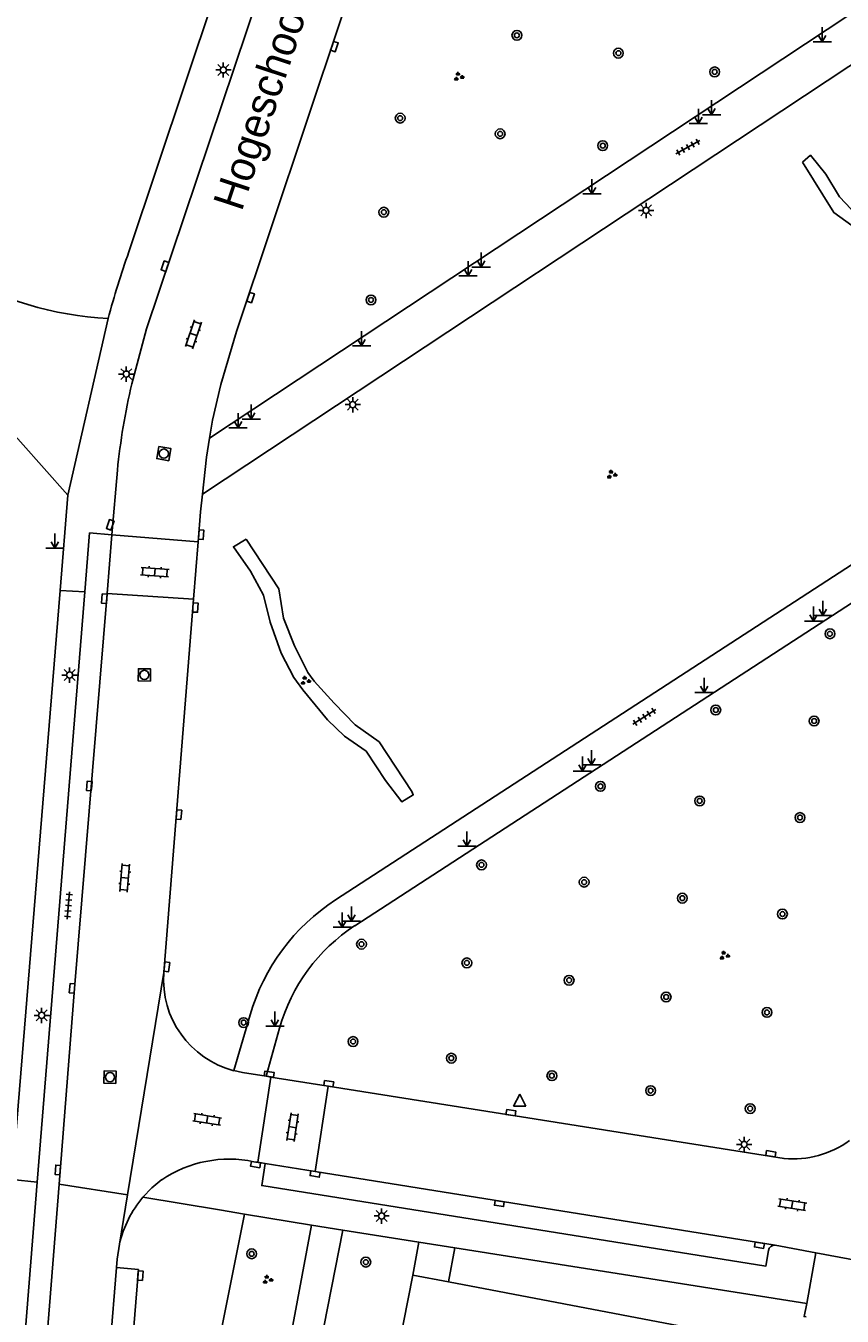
# Model space of a CAD drawing. Extents: x 131000 to 133014, y 396499 to 399001.
# Drawn here: x 131320.7 to 131387.5, y 397286.7 to 397392.1 of the extents above; entities that cross this region are included whole.
import ezdxf

# ---------------------------------------------------------------- set-up
doc = ezdxf.new("R2010")
doc.units = 0
for name, color, linetype in [('gg-afsc-hekwerk', 7, 'Continuous'), ('gg-anno-openbare ruimte label', 7, 'Continuous'), ('gg-bbg-hoofdgebouw', 7, 'Continuous'), ('gg-knt-verharding', 7, 'Continuous'), ('gg-knt-verharding nz', 7, 'Continuous'), ('gt-grn-groengrens', 7, 'Continuous'), ('gt-grn-weggrens', 7, 'Continuous'), ('gt-symb-boom', 7, 'Continuous'), ('gt-symb-groenvak', 7, 'Continuous'), ('gt-symb-klinker verharding', 7, 'Continuous'), ('gt-symb-kolk', 7, 'Continuous'), ('gt-symb-lichtmast', 7, 'Continuous'), ('gt-symb-markant object', 7, 'Continuous'), ('gt-symb-rioolschacht', 7, 'Continuous'), ('gt-symb-tegel verharding', 7, 'Continuous'), ('gt-symb-waterafsluiter', 7, 'Continuous')]:
    doc.layers.add(name, color=color, linetype=linetype)

# ---------------------------------------------------------------- blocks, each defined once
blk = doc.blocks.new('gt0-MARKOB')
at = {"layer": 'gt-symb-markant object'}
for p, q in [((0, 0), (0, 1.2)), ((-0.75, 0), (0.75, 0)), ((0, 0), (-0.3, 0.52)), ((0, 0), (0.3, 0.52))]:
    blk.add_line(p, q, dxfattribs=at)
blk = doc.blocks.new('gt0-BOOM')
at = {"layer": 'gt-symb-boom'}
for radius in [0.4, 0.2]:
    blk.add_circle((0, 0), radius, dxfattribs=at)
blk = doc.blocks.new('gt0-LMAST')
at = {"layer": 'gt-symb-lichtmast'}
for p, q in [((-0.18, 0.17), (-0.45, 0.44)), ((-0.01, 0.25), (-0.01, 0.62)), ((0.17, 0.17), (0.44, 0.44)), ((-0.26, 0), (-0.63, 0)), ((-0.18, -0.18), (-0.45, -0.45)), ((-0.01, -0.25), (-0.01, -0.63)), ((0.44, -0.45), (0.17, -0.18)), ((0.24, 0), (0.62, 0))]:
    blk.add_line(p, q, dxfattribs=at)
blk.add_circle((-0.01, 0), 0.25, dxfattribs=at)
blk = doc.blocks.new('gt0-TEG1')
at = {"layer": 'gt-symb-tegel verharding'}
for p, q in [((-1.12, 0), (1.12, 0)), ((-0.9, -0.25), (-0.9, 0.25)), ((-0.45, -0.25), (-0.45, 0.25)), ((0, -0.25), (0, 0.25)), ((0.45, -0.25), (0.45, 0.25)), ((0.9, -0.25), (0.9, 0.25))]:
    blk.add_line(p, q, dxfattribs=at)
blk = doc.blocks.new('gt0-GRVAK')
at = {"layer": 'gt-symb-groenvak'}
for p, q in [((-0.11, 0.19), (-0.23, 0.24)), ((-0.18, 0.15), (0.09, 0.15)), ((-0.09, 0.21), (-0.16, 0.32)), ((-0.05, 0.21), (-0.05, 0.39)), ((0, 0.21), (0.06, 0.32)), ((0.02, 0.19), (0.13, 0.24)), ((0.26, -0.05), (0.2, 0.06)), ((0.3, -0.05), (0.3, 0.13)), ((0.35, -0.05), (0.41, 0.06)), ((-0.24, -0.23), (-0.36, -0.18)), ((-0.32, -0.26), (-0.05, -0.26)), ((-0.23, -0.21), (-0.29, -0.09)), ((-0.18, -0.2), (-0.18, -0.02)), ((-0.14, -0.21), (-0.07, -0.09)), ((-0.12, -0.23), (0, -0.18)), ((0.24, -0.07), (0.12, -0.02)), ((0.17, -0.11), (0.44, -0.11)), ((0.37, -0.07), (0.49, -0.02))]:
    blk.add_line(p, q, dxfattribs=at)
blk = doc.blocks.new('gt0-KL1')
at = {"layer": 'gt-symb-klinker verharding'}
for p, q in [((-1.15, 0.3), (1.15, 0.3)), ((-1, -0.3), (-1, 0.3)), ((-0.5, 0.3), (-0.5, 0.45)), ((0, -0.3), (0, 0.3)), ((0.5, 0.3), (0.5, 0.45)), ((1, -0.3), (1, 0.3)), ((-1.15, -0.3), (1.15, -0.3)), ((-0.5, -0.45), (-0.5, -0.3)), ((0.5, -0.45), (0.5, -0.3))]:
    blk.add_line(p, q, dxfattribs=at)
blk = doc.blocks.new('gt0-KOLK')
at = {"layer": 'gt-symb-kolk'}
blk.add_lwpolyline([(0, 0), (0.38, 0), (0.38, 0.4), (-0.38, 0.4), (-0.38, 0), (0, 0)], dxfattribs=at)
blk = doc.blocks.new('gt0-RS')
at = {"layer": 'gt-symb-rioolschacht'}
blk.add_lwpolyline([(-0.5, -0.5), (0.5, -0.5), (0.5, 0.5), (-0.5, 0.5)], close=True, dxfattribs=at)
blk.add_circle((0, 0), 0.375, dxfattribs=at)
blk = doc.blocks.new('gt0-WAFSL')
at = {"layer": 'gt-symb-waterafsluiter'}
for p, q in [((-0.5, -0.33), (0, 0.67)), ((0, 0.67), (0.5, -0.33)), ((0.5, -0.33), (-0.5, -0.33))]:
    blk.add_line(p, q, dxfattribs=at)

msp = doc.modelspace()

# ---------------------------------------------------------------- linework, layer by layer
at = {"layer": 'gg-afsc-hekwerk'}
for points in [[(131384.22, 397381.01), (131386.78, 397376.88), (131388.74, 397375.46), (131390.5, 397373.78), (131392.15, 397372), (131392.69, 397371.15), (131394.44, 397366.61), (131394.7, 397364.19), (131397.27, 397360.07)], [(131352.28, 397329.56), (131349.62, 397333.62), (131347.65, 397335.02), (131345.93, 397336.77), (131344.31, 397338.57), (131343.79, 397339.29), (131342.69, 397341.47), (131341.81, 397343.74), (131341.41, 397346.13), (131338.74, 397350.18)]]:
    msp.add_lwpolyline(points, dxfattribs=at)
at = {"layer": 'gg-bbg-hoofdgebouw'}
msp.add_line((131352.36, 397290.02), (131355.29, 397289.47), dxfattribs=at)
for points in [[(131344.63, 397283.38), (131350.82, 397282.16), (131352.36, 397290.02)], [(131355.29, 397289.47), (131374.14, 397285.89), (131373.36, 397281.77), (131380.43, 397280.44), (131378.86, 397272.17)]]:
    msp.add_lwpolyline(points, dxfattribs=at)
at = {"layer": 'gg-knt-verharding'}
for p, q in [((131340.86, 397408.65), (131329.16, 397373.66)), ((131335.76, 397358.44), (131403.77, 397403.49)), ((131408.39, 397402.32), (131335.18, 397353.86)), ((131329.4, 397362.88), (131330.61, 397367.38)), ((131324.17, 397353.78), (131314.75, 397364.39)), ((131400.59, 397356.11), (131346.05, 397320.69)), ((131328.22, 397355.83), (131327.77, 397350.55)), ((131324.17, 397353.78), (131323.53, 397345.99)), ((131399.92, 397352.55), (131347.63, 397318.59)), ((131334.83, 397349.97), (131327.77, 397350.55)), ((131334.83, 397349.97), (131334.45, 397345.27)), ((131323.53, 397345.99), (131319.61, 397297.84)), ((131325.56, 397345.88), (131321.67, 397297.63)), ((131327.38, 397345.75), (131334.45, 397345.27)), ((131334.45, 397345.27), (131332.02, 397314.77)), ((131339.07, 397311.3), (131337.74, 397306.74)), ((131341.47, 397310.21), (131340.38, 397306.28)), ((131340.38, 397306.28), (131340.77, 397306.22)), ((131340.77, 397306.22), (131339.71, 397299.25)), ((131340.77, 397306.22), (131345.45, 397305.48)), ((131344.38, 397298.5), (131345.45, 397305.48)), ((131345.45, 397305.48), (131382.72, 397299.57)), ((131339.71, 397299.25), (131339.38, 397299.3)), ((131340.29, 397299.15), (131339.71, 397299.25)), ((131338.61, 397295.02), (131344.08, 397294.12)), ((131346.66, 397293.71), (131344.63, 397283.38)), ((131352.87, 397292.73), (131346.66, 397293.71)), ((131355.82, 397292.26), (131352.87, 397292.73)), ((131384.57, 397287.7), (131355.82, 397292.26)), ((131385.33, 397291.85), (131382, 397292.47)), ((131390.4, 397290.9), (131385.33, 397291.85))]:
    msp.add_line(p, q, dxfattribs=at)
for points in [[(131330.61, 397367.38), (131346.03, 397413.27), (131346.46, 397417.82)], [(131335.76, 397358.44), (131336, 397359.91), (131336.67, 397362.82), (131337.97, 397367.17), (131352.27, 397409.97)], [(131335.76, 397358.44), (131335.5, 397356.9), (131335.18, 397353.86)], [(131335.18, 397353.86), (131335.02, 397352.42), (131334.83, 397349.97)], [(131327.77, 397350.55), (131325.95, 397350.7), (131325.56, 397345.88)], [(131340.38, 397306.28), (131338.44, 397306.59), (131337.74, 397306.74)], [(131340.29, 397299.15), (131340.02, 397297.34), (131381.22, 397290.75), (131381.44, 397292.05)], [(131320.36, 397259.14), (131318.57, 397259.24), (131321.67, 397297.63)], [(131331.85, 397297.83), (131331.04, 397297.15), (131330.31, 397296.39)], [(131344.08, 397294.12), (131342.19, 397283.89), (131336.59, 397284.94), (131338.61, 397295.02)], [(131328.39, 397292.57), (131328.19, 397291.32), (131328.14, 397290.65)], [(131322.9, 397203.91), (131329.94, 397290.48), (131328.14, 397290.65)], [(131384.53, 397286.61), (131384.36, 397286.64), (131384.57, 397287.7)]]:
    msp.add_lwpolyline(points, dxfattribs=at)
for centre, radius, start, end in [((131328.85, 397395.81), 27.62, 212.161, 267.13), ((131396.95, 397349.62), 71.93, 160.4732, 165.0154), ((131381.85, 397350.44), 53.9, 166.6634, 174.267), ((131355.2, 397306.6), 16.8, 122.9954, 163.7311), ((131355.66, 397306.25), 14.72, 123.015, 164.395), ((131339.67, 397314.16), 7.67, 175.4568, 255.4497), ((131383.48, 397307.32), 7.79, 264.3662, 306.1476), ((131337.35, 397289.67), 9.84, 78.1055, 123.9871), ((131337.31, 397290.48), 9.16, 139.8111, 166.7828), ((131381.94, 397291.96), 0.506, 83.4052, 170.2357)]:
    msp.add_arc(centre, radius, start, end, dxfattribs=at)
at = {"layer": 'gg-knt-verharding nz'}
for p, q in [((131327.77, 397350.55), (131327.38, 397345.75)), ((131344.38, 397298.5), (131340.29, 397299.15)), ((131382, 397292.47), (131344.38, 397298.5)), ((131328.14, 397290.65), (131326.38, 397269.16))]:
    msp.add_line(p, q, dxfattribs=at)
for points in [[(131327.38, 397345.75), (131324.72, 397313.45), (131323.46, 397297.47)], [(131323.46, 397297.47), (131322.48, 397285.11), (131321.22, 397270.23), (131321.24, 397269.59)]]:
    msp.add_lwpolyline(points, dxfattribs=at)
at = {"layer": 'gt-grn-groengrens'}
for p, q in [((131352.36, 397290.02), (131352.87, 397292.73)), ((131355.29, 397289.47), (131355.82, 397292.26))]:
    msp.add_line(p, q, dxfattribs=at)
for points in [[(131397.27, 397360.07), (131397.44, 397359.87), (131398.26, 397360.39), (131396.74, 397362.93), (131395.84, 397365.09), (131395.54, 397367.07), (131393.81, 397371.52), (131392.89, 397372.97), (131391.31, 397374.73), (131389.51, 397376.3), (131388.22, 397377.15), (131387.24, 397378.17), (131386.13, 397380.01), (131384.88, 397381.57), (131384.22, 397381.01)], [(131338.74, 397350.18), (131337.71, 397349.57), (131339.11, 397347.56), (131340.16, 397345.6), (131340.7, 397343.41), (131341.61, 397340.87), (131342.64, 397338.89), (131343.37, 397337.88), (131345.39, 397335.42), (131346.78, 397334.07), (131348.56, 397332.85), (131350.14, 397330.47), (131351.47, 397328.72), (131352.41, 397329.28), (131352.28, 397329.56)]]:
    msp.add_lwpolyline(points, dxfattribs=at)
at = {"layer": 'gt-grn-weggrens'}
for p, q in [((131327.47, 397368.22), (131324.17, 397353.78)), ((131325.56, 397345.88), (131323.53, 397345.99)), ((131329.05, 397296.59), (131332.02, 397314.77)), ((131319.61, 397297.84), (131321.67, 397297.63)), ((131323.46, 397297.47), (131329.05, 397296.59)), ((131329.05, 397296.59), (131328.39, 397292.57)), ((131336.56, 397295.36), (131330.31, 397296.39)), ((131338.61, 397295.02), (131336.56, 397295.36)), ((131346.66, 397293.71), (131344.08, 397294.12)), ((131385.33, 397291.85), (131384.57, 397287.7))]:
    msp.add_line(p, q, dxfattribs=at)

# ---------------------------------------------------------------- block references
at = {"layer": 'gt-symb-boom'}
for p in [(131360.88, 397391.37), (131369.18, 397389.91), (131377.05, 397388.38), (131351.34, 397384.6), (131359.51, 397383.32), (131367.9, 397382.35), (131350, 397376.91), (131348.95, 397369.74), (131386.47, 397342.45), (131377.14, 397336.22), (131385.18, 397335.32), (131367.71, 397329.98), (131375.82, 397328.79), (131384.02, 397327.43), (131357.99, 397323.56), (131366.38, 397322.15), (131374.4, 397320.84), (131382.59, 397319.54), (131348.18, 397317.08), (131356.79, 397315.55), (131365.15, 397314.13), (131373.08, 397312.76), (131381.32, 397311.5), (131338.54, 397310.67), (131347.49, 397309.12), (131355.52, 397307.76), (131363.74, 397306.33), (131371.81, 397305.11), (131379.95, 397303.64), (131339.2, 397291.77), (131348.53, 397291.09)]:
    msp.add_blockref('gt0-BOOM', p, dxfattribs=at)
at = {"layer": 'gt-symb-groenvak'}
for p in [(131356.11, 397387.99), (131368.62, 397355.47), (131343.58, 397338.61), (131377.83, 397316.15), (131340.48, 397289.66)]:
    msp.add_blockref('gt0-GRVAK', p, dxfattribs=at)
at = {"layer": 'gt-symb-klinker verharding'}
for p, rotation in [((131334.44, 397366.92), 71.51067367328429), ((131331.28, 397347.49), -3.9550376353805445), ((131328.82, 397322.51), 85.29819168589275), ((131335.56, 397302.75), -9.094804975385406), ((131342.54, 397302.12), -98.62422873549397), ((131383.39, 397295.79), -9.094804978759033)]:
    msp.add_blockref('gt0-KL1', p, dxfattribs=dict(at, rotation=rotation))
at = {"layer": 'gt-symb-kolk'}
for p, rotation in [((131345.77, 397390.51), -108.59797779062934), ((131332.3, 397372.43), 69.87983420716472), ((131338.92, 397370), -109.21431186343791), ((131327.82, 397351.29), 70.96692019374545), ((131334.87, 397350.57), -94.70180831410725), ((131327.36, 397345.3), 85.75513794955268), ((131334.4, 397344.61), -93.26885295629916), ((131326.12, 397330), 85.41237434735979), ((131333.05, 397327.68), -94.4162834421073), ((131332.06, 397315.25), -97.181878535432), ((131324.72, 397313.45), 85.24111432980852), ((131340.6, 397306.25), -8.219209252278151), ((131345.47, 397305.48), -8.859429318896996), ((131360.36, 397303.11), -8.9726266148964), ((131381.61, 397299.75), -8.340866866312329), ((131323.55, 397298.61), 85.41237434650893), ((131339.55, 397299.26), 171.0273733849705), ((131344.42, 397298.49), 169.0495657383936), ((131359.47, 397296.08), 171.7241071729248), ((131380.74, 397292.67), 170.79203094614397), ((131329.9, 397290), -94.70180831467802)]:
    msp.add_blockref('gt0-KOLK', p, dxfattribs=dict(at, rotation=rotation))
at = {"layer": 'gt-symb-lichtmast'}
for p in [(131336.89, 397388.54), (131371.45, 397377.06), (131328.95, 397363.68), (131347.47, 397361.18), (131324.32, 397339.08), (131322.04, 397311.26), (131379.47, 397300.71), (131349.83, 397294.86)]:
    msp.add_blockref('gt0-LMAST', p, dxfattribs=at)
at = {"layer": 'gt-symb-markant object'}
for p in [(131385.84, 397390.83), (131376.79, 397384.87), (131375.72, 397384.16), (131367.02, 397378.41), (131356.89, 397371.72), (131357.96, 397372.42), (131348.19, 397365.98), (131339.16, 397360), (131338.09, 397359.28), (131323.12, 397349.44), (131385.14, 397343.47), (131385.88, 397343.95), (131376.19, 397337.66), (131366.98, 397331.74), (131366.24, 397331.23), (131356.79, 397325.09), (131347.35, 397318.97), (131346.61, 397318.47), (131341.1, 397310.37)]:
    msp.add_blockref('gt0-MARKOB', p, dxfattribs=at)
at = {"layer": 'gt-symb-rioolschacht'}
for p, rotation in [((131332.02, 397357.18), 80.03848340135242), ((131330.43, 397339.09), 89.19791148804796), ((131327.62, 397306.21), 88.33888795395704)]:
    msp.add_blockref('gt0-RS', p, dxfattribs=dict(at, rotation=rotation))
at = {"layer": 'gt-symb-tegel verharding'}
for p, rotation in [((131374.86, 397382.23), 28.56471819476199), ((131371.3, 397335.66), 33.007061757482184), ((131324.22, 397320.24), 85.29819168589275)]:
    msp.add_blockref('gt0-TEG1', p, dxfattribs=dict(at, rotation=rotation))
at = {"layer": 'gt-symb-waterafsluiter'}
msp.add_blockref('gt0-WAFSL', (131361.11, 397304.16), dxfattribs=at)

# ---------------------------------------------------------------- texts
at = {"layer": 'gg-anno-openbare ruimte label'}
msp.add_text('Hogeschoollaan', height=2.5, rotation=71.8, dxfattribs=at).set_placement((131338.38, 397376.91))

doc.saveas('drawing.dxf')
